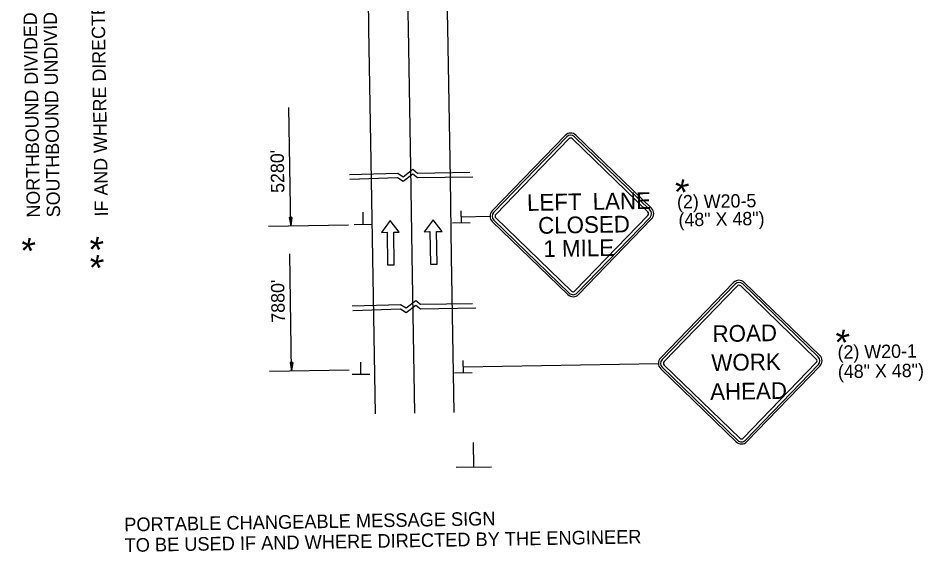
# Model space of a CAD drawing. Extents: x 1676639 to 1677883, y 226447 to 231777.
# Drawn here: x 1677053.1 to 1677459.9, y 226446.6 to 226686.5 of the extents above; entities that cross this region are included whole.
import ezdxf

# ---------------------------------------------------------------- set-up
doc = ezdxf.new("R2010")
doc.units = 0
for name, color, linetype in [('Default', 7, 'Continuous'), ('P_TC_Signs_Temporary', 7, 'Continuous'), ('R_Annotation', 7, 'Continuous'), ('R_MOT', 7, 'Continuous')]:
    doc.layers.add(name, color=color, linetype=linetype)

msp = doc.modelspace()

# ---------------------------------------------------------------- linework, layer by layer
at = {"layer": 'Default'}
for p, q in [((1677210.84, 226681.67), (1677209.68, 226752.04)), ((1677228.57, 226681.96), (1677227.41, 226752.34)), ((1677246.3, 226682.26), (1677245.14, 226752.63)), ((1677211.97, 226613.73), (1677210.84, 226681.67)), ((1677229.61, 226619.57), (1677228.57, 226681.96)), ((1677247.43, 226614.37), (1677246.3, 226682.26)), ((1677175.67, 226593.14), (1677174.79, 226646.37)), ((1677230.27, 226579.87), (1677229.61, 226619.57)), ((1677212.55, 226578.8), (1677211.97, 226613.73)), ((1677248.01, 226579.44), (1677247.43, 226614.37)), ((1677208.27, 226593.8), (1677208.18, 226599.25)), ((1677252.39, 226594.53), (1677252.3, 226599.98)), ((1677176.18, 226596.98), (1677175.03, 226596.96)), ((1677175.03, 226596.96), (1677175.67, 226593.14)), ((1677175.13, 226596.96), (1677175.66, 226593.78)), ((1677175.23, 226596.96), (1677175.65, 226594.44)), ((1677175.32, 226596.96), (1677175.64, 226595.08)), ((1677175.42, 226596.96), (1677175.63, 226595.72)), ((1677175.52, 226596.97), (1677175.62, 226596.36)), ((1677175.7, 226596.97), (1677175.62, 226596.36)), ((1677175.79, 226596.97), (1677175.63, 226595.72)), ((1677175.89, 226596.97), (1677175.64, 226595.08)), ((1677175.99, 226596.97), (1677175.65, 226594.44)), ((1677176.09, 226596.98), (1677175.66, 226593.78)), ((1677176.18, 226596.98), (1677175.67, 226593.14)), ((1677165.69, 226592.98), (1677201.59, 226593.57)), ((1677212.24, 226593.75), (1677204.26, 226593.62)), ((1677256.36, 226594.48), (1677248.38, 226594.35)), ((1677176.07, 226527.95), (1677175.2, 226580.57)), ((1677213.71, 226508.66), (1677212.55, 226578.8)), ((1677231.44, 226508.95), (1677230.27, 226579.87)), ((1677249.17, 226509.25), (1677248.01, 226579.44)), ((1677176.58, 226531.78), (1677175.44, 226531.76)), ((1677175.44, 226531.76), (1677176.07, 226527.95)), ((1677175.53, 226531.76), (1677176.06, 226528.58)), ((1677175.63, 226531.76), (1677176.05, 226529.24)), ((1677175.72, 226531.77), (1677176.04, 226529.88)), ((1677175.82, 226531.77), (1677176.03, 226530.53)), ((1677175.92, 226531.77), (1677176.02, 226531.17)), ((1677176.1, 226531.77), (1677176.02, 226531.17)), ((1677176.19, 226531.77), (1677176.03, 226530.53)), ((1677176.29, 226531.78), (1677176.04, 226529.88)), ((1677176.39, 226531.78), (1677176.05, 226529.24)), ((1677176.49, 226531.78), (1677176.06, 226528.58)), ((1677176.58, 226531.78), (1677176.07, 226527.95)), ((1677207.26, 226526.46), (1677207.17, 226531.91)), ((1677253.34, 226527.13), (1677253.25, 226532.57)), ((1677166.09, 226527.78), (1677202, 226528.38)), ((1677211.23, 226526.41), (1677203.25, 226526.28)), ((1677257.31, 226527.07), (1677249.33, 226526.94)), ((1677258.01, 226484.86), (1677257.83, 226495.76)), ((1677265.95, 226484.76), (1677249.99, 226484.5))]:
    msp.add_line(p, q, dxfattribs=at)
for points in [[(1677202.05, 226616.19), (1677223.77, 226616.88), (1677226.26, 226615.27), (1677230.63, 226618.57), (1677232.69, 226616.9), (1677256.12, 226617.29)], [(1677202.28, 226614.16), (1677223.72, 226614.84), (1677226.21, 226613.23), (1677230.57, 226616.53), (1677232.64, 226614.86), (1677257.58, 226615.27)], [(1677203.37, 226557.19), (1677225.09, 226557.88), (1677227.58, 226556.27), (1677231.94, 226559.57), (1677234.01, 226557.9), (1677257.43, 226558.29)], [(1677203.6, 226555.16), (1677225.04, 226555.85), (1677227.53, 226554.23), (1677231.89, 226557.53), (1677233.96, 226555.87), (1677258.9, 226556.27)]]:
    msp.add_lwpolyline(points, dxfattribs=at)
at = {"layer": 'P_TC_Signs_Temporary'}
for p, q in [((1677266.22, 226599.87), (1677299.07, 226633.83)), ((1677266.89, 226599.22), (1677299.75, 226633.18)), ((1677267.84, 226598.31), (1677300.69, 226632.27)), ((1677302.28, 226632.29), (1677336.24, 226599.44)), ((1677303.19, 226633.24), (1677337.15, 226600.38)), ((1677303.84, 226633.91), (1677337.8, 226601.06)), ((1677300.26, 226562.25), (1677266.3, 226595.1)), ((1677300.91, 226562.92), (1677266.95, 226595.77)), ((1677301.82, 226563.86), (1677267.86, 226596.72)), ((1677336.27, 226597.85), (1677303.41, 226563.89)), ((1677337.21, 226596.94), (1677304.36, 226562.98)), ((1677337.88, 226596.29), (1677305.03, 226562.33)), ((1677341.9, 226533.7), (1677374.75, 226567.66)), ((1677342.58, 226533.05), (1677375.43, 226567.01)), ((1677378.87, 226567.07), (1677412.83, 226534.22)), ((1677379.53, 226567.74), (1677413.49, 226534.89)), ((1677343.52, 226532.14), (1677376.37, 226566.1)), ((1677377.96, 226566.13), (1677411.92, 226533.27)), ((1677377.51, 226497.7), (1677343.55, 226530.55)), ((1677411.95, 226531.68), (1677379.1, 226497.72)), ((1677412.89, 226530.77), (1677380.04, 226496.81)), ((1677413.57, 226530.12), (1677380.71, 226496.16)), ((1677375.94, 226496.08), (1677341.98, 226528.93)), ((1677376.59, 226496.75), (1677342.63, 226529.61))]:
    msp.add_line(p, q, dxfattribs=at)
for centre, radius, start, end in [((1677301.5, 226631.49), 3.38, 45.9497, 135.9497), ((1677301.5, 226631.49), 2.44, 45.9497, 135.9497), ((1677301.5, 226631.49), 1.13, 45.9497, 135.9497), ((1677268.65, 226597.53), 3.38, 135.9497, 225.9497), ((1677268.65, 226597.53), 2.44, 135.9497, 225.9497), ((1677335.46, 226598.63), 1.12, 315.9497, 45.9497), ((1677335.46, 226598.63), 2.44, 315.9497, 45.9497), ((1677335.46, 226598.63), 3.38, 315.9497, 45.9497), ((1677268.65, 226597.53), 1.12, 135.9497, 225.9497), ((1677377.18, 226565.32), 3.38, 45.9497, 135.9497), ((1677377.18, 226565.32), 2.44, 45.9497, 135.9497), ((1677302.61, 226564.67), 2.44, 225.9497, 315.9497), ((1677302.61, 226564.67), 1.13, 225.9497, 315.9497), ((1677377.18, 226565.32), 1.13, 45.9497, 135.9497), ((1677302.61, 226564.67), 3.38, 225.9497, 315.9497), ((1677411.14, 226532.47), 2.44, 315.9497, 45.9497), ((1677411.14, 226532.47), 3.38, 315.9497, 45.9497), ((1677344.33, 226531.36), 3.38, 135.9497, 225.9497), ((1677344.33, 226531.36), 2.44, 135.9497, 225.9497), ((1677344.33, 226531.36), 1.12, 135.9497, 225.9497), ((1677411.14, 226532.47), 1.12, 315.9497, 45.9497), ((1677378.29, 226498.51), 1.13, 225.9497, 315.9497), ((1677378.29, 226498.51), 3.38, 225.9497, 315.9497), ((1677378.29, 226498.51), 2.44, 225.9497, 315.9497)]:
    msp.add_arc(centre, radius, start, end, dxfattribs=at)
at = {"layer": 'R_Annotation'}
for p, q in [((1677252.34, 226597.26), (1677265.27, 226597.47)), ((1677253.3, 226529.85), (1677340.95, 226531.3)), ((1677253.3, 226529.85), (1677340.95, 226531.3))]:
    msp.add_line(p, q, dxfattribs=at)
at = {"layer": 'R_MOT'}
for points in [[(1677224.46, 226590.37), (1677220.37, 226595.5), (1677216.46, 226590.24), (1677218.96, 226590.28), (1677219.22, 226575.57), (1677222.22, 226575.62), (1677221.96, 226590.33)], [(1677243.73, 226590.69), (1677239.64, 226595.81), (1677235.73, 226590.55), (1677238.23, 226590.6), (1677238.48, 226575.89), (1677241.48, 226575.94), (1677241.23, 226590.65)]]:
    msp.add_lwpolyline(points, close=True, dxfattribs=at)

# ---------------------------------------------------------------- texts
at = {"layer": 'Default'}
for s, height, rotation, p in [("5280'", 6, 90.9497, (1677172.85, 226608.01)), ("7880'", 6, 90.9497, (1677173.07, 226549.66)), ('PORTABLE CHANGEABLE MESSAGE SIGN', 6.1199, 0.9497, (1677100.89, 226455.81)), ('TO BE USED IF AND WHERE DIRECTED BY THE ENGINEER', 6.1199, 0.9497, (1677101.04, 226446.58))]:
    msp.add_text(s, height=height, rotation=rotation, dxfattribs=at).set_placement(p)
at = {"layer": 'P_TC_Signs_Temporary'}
for s, p in [('LEFT\u2002LANE', (1677281.93, 226599.87)), ('CLOSED', (1677286.94, 226589.58)), ('1 MILE', (1677289.31, 226579.12)), (' ROAD ', (1677362.56, 226540.87)), ('WORK', (1677364.81, 226527.89)), (' AHEAD ', (1677361.47, 226514.81))]:
    msp.add_text(s, height=7.5, rotation=0.9497, dxfattribs=at).set_placement(p)
at = {"layer": 'R_Annotation'}
for s, height, rotation, p in [('SOUTHBOUND UNDIVIDED HIGHWAY ONE (1) SIGN REQUIRED', 6, 90.9497, (1677072.02, 226597.08)), ('NORTHBOUND DIVIDED HIGHWAY TWO (2) SIGNS REQUIRED ', 6, 90.9497, (1677063.03, 226596.94)), ('IF AND WHERE DIRECTED BY THE ENGINEER', 6, 90.9497, (1677093.61, 226597.44)), ('*', 12, 135.9497, (1677359.87, 226615.17)), ('(2) W20-5', 6, 0.9497, (1677349.35, 226600.96)), ('(48" X 48")', 6, 0.9497, (1677350.02, 226592.91)), ('*', 12, 135.9497, (1677066.09, 226588.8)), ('*', 12, 135.9497, (1677096.68, 226589.31)), ('*', 12, 135.9497, (1677096.82, 226581.13)), ('*', 12, 135.9497, (1677432.06, 226547.61)), ('(2) W20-1', 6, 0.9497, (1677421.54, 226533.4)), ('(48" X 48")', 6, 0.9497, (1677421.68, 226524.66))]:
    msp.add_text(s, height=height, rotation=rotation, dxfattribs=at).set_placement(p)

doc.saveas('drawing.dxf')
